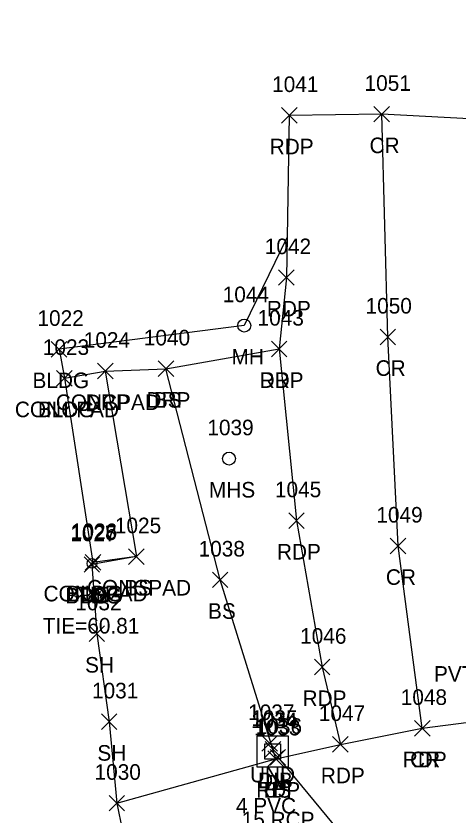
# Model space of a CAD drawing. Extents: x 1505684 to 1510253, y 730355 to 731397.
# Drawn here: x 1510021.1 to 1510077.9, y 730905.9 to 731008.5 of the extents above; entities that cross this region are included whole.
import ezdxf

# ---------------------------------------------------------------- set-up
doc = ezdxf.new("R2010")
doc.units = 0
for name, color, linetype in [('C_A', 7, 'Continuous'), ('C_C', 7, 'Continuous'), ('C_I', 7, 'Continuous'), ('CBP', 7, 'Continuous'), ('D_A', 7, 'Continuous'), ('D_C', 7, 'Continuous'), ('D_I', 7, 'Continuous'), ('D_TIC', 7, 'Continuous'), ('DCP', 7, 'Continuous'), ('DS', 7, 'Continuous'), ('L_A', 7, 'Continuous'), ('L_I', 7, 'Continuous'), ('L_TIC', 7, 'Continuous'), ('LBC', 7, 'Continuous'), ('LELB', 7, 'Continuous'), ('LS', 7, 'Continuous'), ('LSOGP', 7, 'Continuous'), ('P_A', 7, 'Continuous'), ('P_I', 7, 'Continuous'), ('P_TIC', 7, 'Continuous'), ('PET', 7, 'Continuous'), ('PRC', 7, 'Continuous'), ('R_A', 7, 'Continuous'), ('R_I', 7, 'Continuous'), ('R_TIC', 7, 'Continuous'), ('RDP', 7, 'Continuous'), ('S_C', 7, 'Continuous'), ('U_A', 7, 'Continuous'), ('U_I', 7, 'Continuous'), ('USMH', 7, 'Continuous'), ('UUMH', 7, 'Continuous')]:
    doc.layers.add(name, color=color, linetype=linetype)

msp = doc.modelspace()

# ---------------------------------------------------------------- linework, layer by layer
at = {"layer": 'CBP'}
for radius in [0.625, 0.0833]:
    msp.add_circle((1510030.87, 730938.19), radius, dxfattribs=at)
at = {"layer": 'D_TIC'}
for points in [[(1510052.71, 730914.08), (1510054.71, 730916.08)], [(1510054.71, 730914.08), (1510052.71, 730916.08)], [(1510053.12, 730913.33), (1510055.12, 730915.33)], [(1510055.12, 730913.33), (1510053.12, 730915.33)], [(1510053.75, 730912.3), (1510055.75, 730914.3)], [(1510055.75, 730912.3), (1510053.75, 730914.3)]]:
    msp.add_lwpolyline(points, dxfattribs=at)
at = {"layer": 'DCP'}
msp.add_lwpolyline([(1510054.75, 730913.3), (1510075.66, 730888.03)], dxfattribs=at)
at = {"layer": 'DS'}
for p, q in [((1510052.08, 730916.04), (1510056.08, 730916.04)), ((1510052.08, 730912.04), (1510052.08, 730916.04)), ((1510056.08, 730916.04), (1510056.08, 730912.04)), ((1510053.08, 730913.04), (1510053.08, 730915.04)), ((1510053.08, 730915.04), (1510055.08, 730915.04)), ((1510055.08, 730915.04), (1510055.08, 730913.04)), ((1510054.09, 730914.04), (1510054.09, 730914.04)), ((1510054.09, 730914.04), (1510054.09, 730914.04)), ((1510055.08, 730913.04), (1510053.08, 730913.04)), ((1510056.08, 730912.04), (1510052.08, 730912.04))]:
    msp.add_line(p, q, dxfattribs=at)
at = {"layer": 'L_TIC'}
for points in [[(1510025.63, 730964.7), (1510027.63, 730966.7)], [(1510027.63, 730964.7), (1510025.63, 730966.7)], [(1510031.58, 730961.89), (1510033.58, 730963.89)], [(1510033.58, 730961.89), (1510031.58, 730963.89)], [(1510039.38, 730962.19), (1510041.38, 730964.19)], [(1510041.38, 730962.19), (1510039.38, 730964.19)], [(1510026.32, 730960.97), (1510028.32, 730962.97)], [(1510028.32, 730960.97), (1510026.32, 730962.97)], [(1510026.32, 730960.97), (1510028.32, 730962.97)], [(1510028.32, 730960.97), (1510026.32, 730962.97)], [(1510029.99, 730937.32), (1510031.99, 730939.32)], [(1510031.99, 730937.32), (1510029.99, 730939.32)], [(1510029.99, 730937.32), (1510031.99, 730939.32)], [(1510031.99, 730937.32), (1510029.99, 730939.32)], [(1510035.58, 730938.07), (1510037.58, 730940.07)], [(1510037.58, 730938.07), (1510035.58, 730940.07)], [(1510035.58, 730938.07), (1510037.58, 730940.07)], [(1510037.58, 730938.07), (1510035.58, 730940.07)], [(1510029.85, 730937.05), (1510031.85, 730939.05)], [(1510031.85, 730937.05), (1510029.85, 730939.05)], [(1510029.85, 730937.05), (1510031.85, 730939.05)], [(1510031.85, 730937.05), (1510029.85, 730939.05)], [(1510046.34, 730935.08), (1510048.34, 730937.08)], [(1510048.34, 730935.08), (1510046.34, 730937.08)], [(1510030.49, 730928.17), (1510032.49, 730930.17)], [(1510032.49, 730928.17), (1510030.49, 730930.17)], [(1510032.07, 730916.86), (1510034.07, 730918.86)], [(1510034.07, 730916.86), (1510032.07, 730918.86)], [(1510053.48, 730912.11), (1510055.48, 730914.11)], [(1510055.48, 730912.11), (1510053.48, 730914.11)]]:
    msp.add_lwpolyline(points, dxfattribs=at)
at = {"layer": 'LBC'}
msp.add_lwpolyline([(1510026.63, 730965.7), (1510027.32, 730961.97), (1510030.99, 730938.32), (1510030.85, 730938.05)], dxfattribs=at)
at = {"layer": 'LELB'}
for points in [[(1510054.48, 730913.11), (1510047.34, 730936.08), (1510040.38, 730963.19)], [(1510036.58, 730939.07), (1510030.85, 730938.05)]]:
    msp.add_lwpolyline(points, dxfattribs=at)
at = {"layer": 'LS'}
msp.add_lwpolyline([(1510027.32, 730961.97), (1510032.58, 730962.89), (1510036.58, 730939.07), (1510030.99, 730938.32)], dxfattribs=at)
at = {"layer": 'LSOGP'}
msp.add_lwpolyline([(1510147.56, 730990.16), (1510122.02, 730991.61), (1510112.96, 730993.53), (1510106.38, 730998.05), (1510099.22, 731008.49), (1510092.66, 730994.6), (1510089.68, 730994.89), (1510088.68, 730994.91), (1510088.15, 730994.82), (1510068.1, 730995.88), (1510056.23, 730995.73), (1510056.13, 730990.53), (1510056.04, 730985.32), (1510055.94, 730980.11), (1510050.44, 730968.74), (1510026.63, 730965.7), (1510027.32, 730961.97), (1510030.99, 730938.32), (1510030.85, 730938.05), (1510031.49, 730929.17), (1510033.07, 730917.86), (1510034.06, 730907.41), (1510037.72, 730889.42)], dxfattribs=at)
at = {"layer": 'P_TIC'}
for points in [[(1510055.23, 730994.73), (1510057.23, 730996.73)], [(1510057.23, 730994.73), (1510055.23, 730996.73)], [(1510067.1, 730994.88), (1510069.1, 730996.88)], [(1510069.1, 730994.88), (1510067.1, 730996.88)], [(1510054.85, 730973.91), (1510056.85, 730975.91)], [(1510056.85, 730973.91), (1510054.85, 730975.91)], [(1510067.89, 730966.28), (1510069.89, 730968.28)], [(1510069.89, 730966.28), (1510067.89, 730968.28)], [(1510053.93, 730964.73), (1510055.93, 730966.73)], [(1510055.93, 730964.73), (1510053.93, 730966.73)], [(1510056.15, 730942.69), (1510058.15, 730944.69)], [(1510058.15, 730942.69), (1510056.15, 730944.69)], [(1510069.2, 730939.44), (1510071.2, 730941.44)], [(1510071.2, 730939.44), (1510069.2, 730941.44)], [(1510059.45, 730923.88), (1510061.45, 730925.88)], [(1510061.45, 730923.88), (1510059.45, 730925.88)], [(1510072.32, 730916.02), (1510074.32, 730918.02)], [(1510074.32, 730916.02), (1510072.32, 730918.02)], [(1510072.32, 730916.02), (1510074.32, 730918.02)], [(1510074.32, 730916.02), (1510072.32, 730918.02)], [(1510061.8, 730913.96), (1510063.8, 730915.96)], [(1510063.8, 730913.96), (1510061.8, 730915.96)], [(1510061.8, 730913.96), (1510063.8, 730915.96)], [(1510063.8, 730913.96), (1510061.8, 730915.96)], [(1510053.48, 730912.11), (1510055.48, 730914.11)], [(1510055.48, 730912.11), (1510053.48, 730914.11)], [(1510033.06, 730906.41), (1510035.06, 730908.41)], [(1510035.06, 730906.41), (1510033.06, 730908.41)]]:
    msp.add_lwpolyline(points, dxfattribs=at)
at = {"layer": 'PET'}
for points in [[(1510056.23, 730995.73), (1510055.85, 730974.91), (1510054.93, 730965.73), (1510057.15, 730943.69), (1510060.45, 730924.88), (1510062.8, 730914.96)], [(1510034.06, 730907.41), (1510054.48, 730913.11), (1510062.8, 730914.96), (1510073.32, 730917.02), (1510090.95, 730919.3), (1510096.42, 730920.57), (1510098.6, 730904.88), (1510099.53, 730892.16), (1510091.79, 730891.36), (1510076.9, 730888.23), (1510070.14, 730887.02), (1510042.84, 730876.21)]]:
    msp.add_lwpolyline(points, dxfattribs=at)
at = {"layer": 'PRC'}
msp.add_lwpolyline([(1510073.32, 730917.02), (1510070.2, 730940.44), (1510068.89, 730967.28), (1510068.1, 730995.88)], dxfattribs=at)
at = {"layer": 'R_TIC'}
for points in [[(1510053.93, 730964.73), (1510055.93, 730966.73)], [(1510055.93, 730964.73), (1510053.93, 730966.73)], [(1510031.58, 730961.89), (1510033.58, 730963.89)], [(1510033.58, 730961.89), (1510031.58, 730963.89)], [(1510039.38, 730962.19), (1510041.38, 730964.19)], [(1510041.38, 730962.19), (1510039.38, 730964.19)]]:
    msp.add_lwpolyline(points, dxfattribs=at)
at = {"layer": 'RDP'}
msp.add_lwpolyline([(1510032.58, 730962.89), (1510040.38, 730963.19), (1510054.93, 730965.73)], dxfattribs=at)
at = {"layer": 'USMH'}
for p, q in [((1510048.48, 730951.65), (1510048.48, 730951.65)), ((1510049.31, 730951.65), (1510049.31, 730951.65))]:
    msp.add_line(p, q, dxfattribs=at)
msp.add_circle((1510048.48, 730951.65), 0.833, dxfattribs=at)
at = {"layer": 'UUMH'}
for p, q in [((1510050.44, 730968.74), (1510050.44, 730968.74)), ((1510051.27, 730968.74), (1510051.27, 730968.74))]:
    msp.add_line(p, q, dxfattribs=at)
msp.add_circle((1510050.44, 730968.74), 0.833, dxfattribs=at)

# ---------------------------------------------------------------- texts
at = {"layer": 'C_A'}
msp.add_text('TIE', height=2, dxfattribs=at).set_placement((1510028.94, 730933.19))
at = {"layer": 'C_C'}
msp.add_text('TIE=60.81', height=2, dxfattribs=at).set_placement((1510024.54, 730929.19))
at = {"layer": 'C_I'}
msp.add_text('1028', height=2, dxfattribs=at).set_placement((1510028.09, 730941.19))
at = {"layer": 'D_A'}
for s, p in [('UND', (1510051.18, 730910.08)), ('DIB', (1510052.22, 730909.33)), ('DI', (1510053.14, 730909.04)), ('P', (1510054.12, 730908.3))]:
    msp.add_text(s, height=2, dxfattribs=at).set_placement(p)
at = {"layer": 'D_C'}
for s, p in [('4 PVC', (1510049.37, 730906.08)), ('15 RCP', (1510050.11, 730904.3))]:
    msp.add_text(s, height=2, dxfattribs=at).set_placement(p)
at = {"layer": 'D_I'}
for s, p in [('1037', (1510050.94, 730918.08)), ('1034', (1510051.32, 730917.04)), ('1035', (1510051.34, 730917.33)), ('1036', (1510051.92, 730916.3))]:
    msp.add_text(s, height=2, dxfattribs=at).set_placement(p)
at = {"layer": 'L_A'}
for s, p in [('BLDG', (1510023.22, 730960.7)), ('CONCPAD', (1510026.22, 730957.89)), ('BS', (1510038.82, 730958.19)), ('CONCPAD', (1510020.96, 730956.97)), ('BLDG', (1510023.91, 730956.97)), ('CONCPAD', (1510030.23, 730934.07)), ('BS', (1510035.02, 730934.07)), ('CONCPAD', (1510024.64, 730933.32)), ('BLDG', (1510027.44, 730933.05)), ('BLDG', (1510027.58, 730933.32)), ('BS', (1510029.29, 730933.05)), ('BS', (1510045.78, 730931.08)), ('SH', (1510029.98, 730924.17)), ('SH', (1510031.56, 730912.86)), ('BS', (1510052.92, 730908.11))]:
    msp.add_text(s, height=2, dxfattribs=at).set_placement(p)
at = {"layer": 'L_I'}
for s, p in [('1022', (1510023.86, 730968.7)), ('1024', (1510029.81, 730965.89)), ('1040', (1510037.53, 730966.19)), ('1023', (1510024.55, 730964.97)), ('1023', (1510024.55, 730964.97)), ('1026', (1510028.16, 730941.32)), ('1026', (1510028.16, 730941.32)), ('1025', (1510033.81, 730942.07)), ('1025', (1510033.81, 730942.07)), ('1027', (1510028.08, 730941.05)), ('1027', (1510028.08, 730941.05)), ('1038', (1510044.57, 730939.08)), ('1032', (1510028.72, 730932.17)), ('1031', (1510030.87, 730920.86)), ('1033', (1510051.71, 730916.11))]:
    msp.add_text(s, height=2, dxfattribs=at).set_placement(p)
at = {"layer": 'P_A'}
for s, p in [('RDP', (1510053.71, 730990.73)), ('CR', (1510066.54, 730990.88)), ('RDP', (1510053.34, 730969.91)), ('CR', (1510067.32, 730962.28)), ('RDP', (1510052.41, 730960.73)), ('RDP', (1510054.64, 730938.69)), ('CR', (1510068.64, 730935.44)), ('RDP', (1510057.93, 730919.88)), ('RDP', (1510070.81, 730912.02)), ('CR', (1510071.75, 730912.02)), ('RDP', (1510060.28, 730909.96)), ('RDP', (1510060.28, 730909.96)), ('RDP', (1510051.97, 730908.11))]:
    msp.add_text(s, height=2, dxfattribs=at).set_placement(p)
at = {"layer": 'P_I'}
for s, p in [('1041', (1510054.02, 730998.73)), ('1051', (1510065.9, 730998.88)), ('1042', (1510053.08, 730977.91)), ('1050', (1510066.03, 730970.28)), ('1043', (1510052.15, 730968.73)), ('1045', (1510054.38, 730946.69)), ('1049', (1510067.42, 730943.44)), ('1046', (1510057.62, 730927.88)), ('1048', (1510070.55, 730920.02)), ('1048', (1510070.55, 730920.02)), ('1047', (1510060.02, 730917.96)), ('1047', (1510060.02, 730917.96)), ('1033', (1510051.71, 730916.11)), ('1030', (1510031.2, 730910.41))]:
    msp.add_text(s, height=2, dxfattribs=at).set_placement(p)
at = {"layer": 'R_A'}
for p in [(1510052.41, 730960.73), (1510030.07, 730957.89), (1510037.87, 730958.19)]:
    msp.add_text('DRP', height=2, dxfattribs=at).set_placement(p)
at = {"layer": 'R_I'}
for s, p in [('1043', (1510052.15, 730968.73)), ('1024', (1510029.81, 730965.89)), ('1040', (1510037.53, 730966.19))]:
    msp.add_text(s, height=2, dxfattribs=at).set_placement(p)
at = {"layer": 'S_C'}
msp.add_text('PVT RED MILL DR', height=2, dxfattribs=at).set_placement((1510074.82, 730923))
at = {"layer": 'U_A'}
for s, p in [('MH', (1510048.8, 730963.74)), ('MHS', (1510045.9, 730946.65))]:
    msp.add_text(s, height=2, dxfattribs=at).set_placement(p)
at = {"layer": 'U_I'}
for s, p in [('1044', (1510047.67, 730971.74)), ('1039', (1510045.7, 730954.65))]:
    msp.add_text(s, height=2, dxfattribs=at).set_placement(p)

doc.saveas('drawing.dxf')
